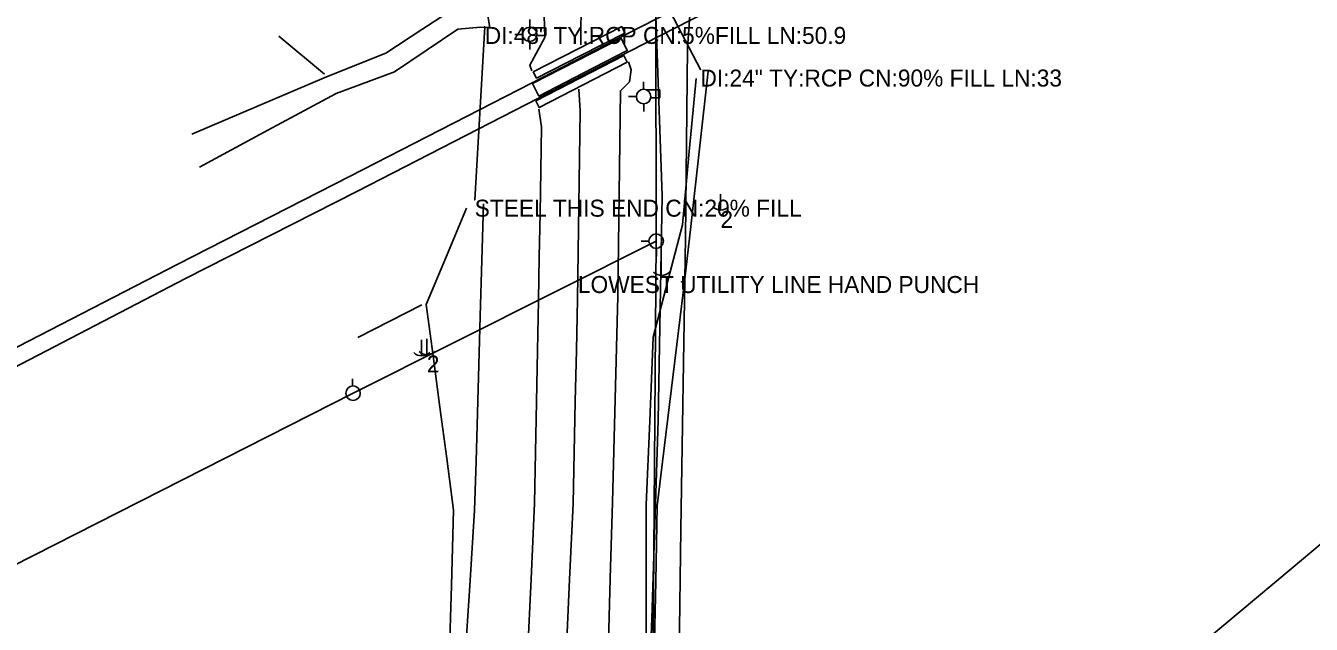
# Model space of a CAD drawing. Extents: x 1707085 to 1720058, y 548761 to 560063.
# Drawn here: x 1712315.3 to 1712693.8, y 549836.8 to 550013 of the extents above; entities that cross this region are included whole.
import ezdxf

# ---------------------------------------------------------------- set-up
doc = ezdxf.new("R2010")
doc.units = 0
for name, color, linetype in [('22', 7, 'Continuous'), ('3', 7, 'Continuous'), ('R_Water Annot', 7, 'Continuous'), ('S_DRG_PT_SYM', 7, 'Continuous'), ('S_EDGE_PAVEMENT', 7, 'Continuous'), ('S_ELECTRIC_UTILITIES_ANNOT', 7, 'Continuous'), ('S_GAS_UTILITIES', 7, 'Continuous'), ('S_MSC_PT_SYM', 7, 'Continuous'), ('S_PAVEMENT_CROWN', 7, 'Continuous'), ('S_SIDE_DRAIN_ANNOT', 7, 'Continuous'), ('S_UTILITY_POLE', 7, 'Continuous'), ('S_UTILITY_POLE_ANNOT', 7, 'Continuous'), ('S_UTL_PT_SYM', 7, 'Continuous')]:
    doc.layers.add(name, color=color, linetype=linetype)

msp = doc.modelspace()

# ---------------------------------------------------------------- linework, layer by layer
for points in [[(1712449.32, 550057.1), (1712439.4, 550041.45), (1712442.55, 550018.72), (1712431.95, 550011.83), (1712421.36, 550004.94), (1712403.89, 549997.96), (1712384.06, 549989.51), (1712364.23, 549981.06)], [(1712452.56, 550057.8), (1712451.58, 550039.11), (1712450.6, 550020.42), (1712452, 550012.47), (1712449.18, 550012.57), (1712442.51, 550011.92), (1712423.88, 549999.42), (1712406.74, 549993.06), (1712386.61, 549982.2), (1712366.49, 549971.34)], [(1712403.31, 549998.67), (1712389.85, 550009.89)], [(1712516.18, 549999.6), (1712513.67, 549976.72), (1712511.17, 549953.84), (1712509.32, 549938.49), (1712507.47, 549923.14), (1712505.92, 549910.27), (1712504.37, 549897.4), (1712502.81, 549884.54), (1712501.26, 549871.67), (1712500.82, 549849.4), (1712500.38, 549827.13), (1712500.22, 549810.79), (1712500.05, 549794.46), (1712518.8, 549793.53), (1712537.55, 549792.61), (1712556.3, 549791.68), (1712575.05, 549790.76), (1712588.15, 549794.26), (1712601.26, 549797.76), (1712614.36, 549801.26), (1712627.46, 549804.76)], [(1712512.67, 549997.47), (1712510.66, 549975.93), (1712508.64, 549954.38), (1712504.35, 549937.83), (1712500.05, 549921.28), (1712499.04, 549896.62), (1712498.02, 549871.95), (1712498, 549849.31), (1712497.97, 549826.67)], [(1712450.13, 549960.52), (1712449.65, 549943.98), (1712449.16, 549927.44), (1712448.74, 549913.18), (1712448.32, 549898.91), (1712447.91, 549884.64), (1712447.49, 549870.37), (1712446.03, 549848.12), (1712444.58, 549825.86), (1712443.13, 549803.61), (1712441.67, 549781.36), (1712441.33, 549777.17), (1712439.1, 549763.29), (1712436.87, 549749.41), (1712435.25, 549741.91), (1712433.87, 549729.68), (1712428.48, 549723.04), (1712424.13, 549714.66), (1712415.06, 549699.57), (1712406, 549684.47), (1712392.91, 549666.42), (1712379.82, 549648.36), (1712369.03, 549636.94), (1712358.25, 549625.52)], [(1712445.12, 549959.28), (1712439.18, 549945.1), (1712433.24, 549930.92), (1712435.25, 549915.78), (1712437.26, 549900.65), (1712439.28, 549885.52), (1712441.29, 549870.38), (1712440.63, 549848.2), (1712439.98, 549826.01), (1712439.32, 549803.82), (1712438.67, 549781.64), (1712438.35, 549777.49), (1712437.11, 549764.29), (1712435.86, 549751.09), (1712435.54, 549749.77), (1712432.09, 549741.95), (1712428.34, 549731.72), (1712421.02, 549715.67), (1712413.21, 549700.34), (1712405.41, 549685)], [(1712413.13, 549921.2), (1712431.91, 549930.83)], [(1712657.85, 549827.96), (1712672.84, 549840.5), (1712687.84, 549853.05), (1712700.01, 549863.27)]]:
    msp.add_lwpolyline(points)
at = {"layer": '22'}
for p, q in [((1712492.4, 550010.61), (1712547.07, 550038.73)), ((1712493.21, 550005.51), (1712555.91, 550037.61)), ((1712463.69, 550012.56), (1712463.69, 550014.8)), ((1712461.6, 550010.42), (1712459.27, 550010.42)), ((1712464.27, 549996.1), (1712492.4, 550010.61)), ((1712468.49, 550012.4), (1712464.62, 550012.4)), ((1712468.49, 550010.08), (1712468.49, 550012.4)), ((1712463.77, 550006.01), (1712463.77, 550008.33)), ((1712468.49, 550010.08), (1712465.78, 550010.08)), ((1712466.25, 549991.68), (1712493.21, 550005.51)), ((1712410.66, 549968.61), (1712464.27, 549996.1)), ((1712497.22, 549994.24), (1712497.22, 549996.48)), ((1712412.81, 549964.19), (1712466.25, 549991.68)), ((1712495.13, 549992.1), (1712492.8, 549992.1)), ((1712502.02, 549994.08), (1712498.15, 549994.08)), ((1712502.02, 549991.76), (1712499.31, 549991.76)), ((1712502.02, 549991.76), (1712502.02, 549994.08)), ((1712497.3, 549987.69), (1712497.3, 549990.01)), ((1712360.1, 549942.79), (1712410.66, 549968.61)), ((1712362.36, 549938.57), (1712412.81, 549964.19)), ((1712304.76, 549914.22), (1712360.1, 549942.79)), ((1712306.81, 549909.7), (1712362.36, 549938.57))]:
    msp.add_line(p, q, dxfattribs=at)
for points in [[(1712464.7, 549999.43), (1712465.72, 549997.54), (1712478.71, 550004.17), (1712491.7, 550010.8), (1712490.77, 550012.73), (1712477.74, 550006.08)], [(1712490.63, 550009.36), (1712492.42, 550005.68), (1712479.43, 549998.97), (1712466.43, 549992.25), (1712464.54, 549995.95), (1712477.59, 550002.65)], [(1712465.46, 549990.9), (1712466.51, 549988.88), (1712479.47, 549995.59), (1712492.43, 550002.29), (1712491.41, 550004.18), (1712478.44, 549997.54)]]:
    msp.add_lwpolyline(points, close=True, dxfattribs=at)
for centre in [(1712463.69, 550010.44), (1712497.22, 549992.12)]:
    msp.add_circle(centre, 2.13, dxfattribs=at)
at = {"layer": '3'}
for p, q in [((1712513.96, 550000.07), (1712498.6, 550029.64)), ((1712450.45, 550012.61), (1712447.5, 549961.76))]:
    msp.add_line(p, q, dxfattribs=at)
at = {"layer": 'R_Water Annot'}
for p, q in [((1712511.52, 550025.76), (1712510.15, 550006.45)), ((1712510.15, 550006.45), (1712509.57, 549950.51)), ((1712509.57, 549950.51), (1712508.17, 549864.7)), ((1712508.17, 549864.7), (1712507.43, 549804.25))]:
    msp.add_line(p, q, dxfattribs=at)
at = {"layer": 'S_DRG_PT_SYM'}
for points in [[(1712450.45, 550012.61), (1712450.45, 550012.66), (1712450.45, 550012.61), (1712450.4, 550012.61), (1712450.45, 550012.61), (1712450.45, 550012.56), (1712450.45, 550012.61), (1712450.5, 550012.61)], [(1712513.96, 550000.07), (1712513.96, 550000.12), (1712513.96, 550000.07), (1712513.91, 550000.07), (1712513.96, 550000.07), (1712513.96, 550000.02), (1712513.96, 550000.07), (1712514.01, 550000.07)], [(1712447.5, 549961.76), (1712447.5, 549961.81), (1712447.5, 549961.76), (1712447.45, 549961.76), (1712447.5, 549961.76), (1712447.5, 549961.71), (1712447.5, 549961.76), (1712447.55, 549961.76)]]:
    msp.add_lwpolyline(points, dxfattribs=at)
at = {"layer": 'S_EDGE_PAVEMENT'}
for points in [[(1712467.77, 550022.58), (1712468.12, 550009.49), (1712463.76, 550001.4), (1712464.35, 549999.67)], [(1712492.77, 550002.31), (1712493.53, 550000.02), (1712493.07, 549996.49), (1712490.38, 549993.82), (1712490.2, 549978.71), (1712490.03, 549963.6), (1712489.85, 549948.48), (1712489.68, 549933.37), (1712489.27, 549918.2), (1712488.86, 549903.03), (1712488.45, 549887.86), (1712488.04, 549872.68), (1712487.4, 549850.22), (1712486.77, 549827.75)], [(1712492.77, 550002.31), (1712493.53, 550000.02), (1712493.07, 549996.49), (1712490.38, 549993.82), (1712490.2, 549978.71), (1712490.03, 549963.6), (1712489.85, 549948.48), (1712489.68, 549933.37), (1712489.27, 549918.2), (1712488.86, 549903.03), (1712488.45, 549887.86), (1712488.04, 549872.68), (1712487.4, 549850.22), (1712486.77, 549827.75)], [(1712466.43, 549988.37), (1712467.17, 549983.23), (1712466.95, 549970.47), (1712466.73, 549957.72), (1712466.52, 549944.96), (1712466.3, 549932.21), (1712466, 549917.25), (1712465.71, 549902.29), (1712465.42, 549887.33), (1712465.12, 549872.38), (1712464.08, 549850.01), (1712463.03, 549827.64)], [(1712466.43, 549988.37), (1712467.17, 549983.23), (1712466.95, 549970.47), (1712466.73, 549957.72), (1712466.52, 549944.96), (1712466.3, 549932.21), (1712466, 549917.25), (1712465.71, 549902.29), (1712465.42, 549887.33), (1712465.12, 549872.38), (1712464.08, 549850.01), (1712463.03, 549827.64)]]:
    msp.add_lwpolyline(points, dxfattribs=at)
at = {"layer": 'S_GAS_UTILITIES'}
for p, q in [((1712500.56, 550022.14), (1712502.65, 549962.94)), ((1712502.65, 549962.94), (1712501.5, 549896.8)), ((1712501.5, 549896.8), (1712499.66, 549838.6)), ((1712499.66, 549838.6), (1712496.86, 549773.59))]:
    msp.add_line(p, q, dxfattribs=at)
at = {"layer": 'S_MSC_PT_SYM'}
for points in [[(1712492.4, 550010.61), (1712492.4, 550010.66), (1712492.4, 550010.61), (1712492.35, 550010.61), (1712492.4, 550010.61), (1712492.4, 550010.56), (1712492.4, 550010.61), (1712492.45, 550010.61)], [(1712493.21, 550005.51), (1712493.21, 550005.56), (1712493.21, 550005.51), (1712493.16, 550005.51), (1712493.21, 550005.51), (1712493.21, 550005.46), (1712493.21, 550005.51), (1712493.26, 550005.51)], [(1712464.27, 549996.1), (1712464.27, 549996.15), (1712464.27, 549996.1), (1712464.22, 549996.1), (1712464.27, 549996.1), (1712464.27, 549996.05), (1712464.27, 549996.1), (1712464.32, 549996.1)], [(1712466.25, 549991.68), (1712466.25, 549991.73), (1712466.25, 549991.68), (1712466.2, 549991.68), (1712466.25, 549991.68), (1712466.25, 549991.63), (1712466.25, 549991.68), (1712466.3, 549991.68)], [(1712410.66, 549968.61), (1712410.66, 549968.66), (1712410.66, 549968.61), (1712410.61, 549968.61), (1712410.66, 549968.61), (1712410.66, 549968.56), (1712410.66, 549968.61), (1712410.71, 549968.61)], [(1712412.81, 549964.19), (1712412.81, 549964.24), (1712412.81, 549964.19), (1712412.76, 549964.19), (1712412.81, 549964.19), (1712412.81, 549964.14), (1712412.81, 549964.19), (1712412.86, 549964.19)], [(1712360.1, 549942.79), (1712360.1, 549942.84), (1712360.1, 549942.79), (1712360.05, 549942.79), (1712360.1, 549942.79), (1712360.1, 549942.74), (1712360.1, 549942.79), (1712360.15, 549942.79)], [(1712362.36, 549938.57), (1712362.36, 549938.62), (1712362.36, 549938.57), (1712362.31, 549938.57), (1712362.36, 549938.57), (1712362.36, 549938.52), (1712362.36, 549938.57), (1712362.41, 549938.57)]]:
    msp.add_lwpolyline(points, dxfattribs=at)
at = {"layer": 'S_PAVEMENT_CROWN'}
for points in [[(1712478.75, 550007.31), (1712478.84, 550022.01)], [(1712478.84, 550022.01), (1712478.75, 550007.31)], [(1712478.11, 549994.32), (1712478.54, 549987.96), (1712478.34, 549974.08), (1712478.15, 549960.21), (1712477.95, 549946.33), (1712477.76, 549932.46), (1712477.43, 549917.42), (1712477.1, 549902.39), (1712476.78, 549887.35), (1712476.45, 549872.32), (1712475.42, 549849.98), (1712474.4, 549827.65)], [(1712478.11, 549994.32), (1712478.54, 549987.96), (1712478.34, 549974.08), (1712478.15, 549960.21), (1712477.95, 549946.33), (1712477.76, 549932.46), (1712477.43, 549917.42), (1712477.1, 549902.39), (1712476.78, 549887.35), (1712476.45, 549872.32), (1712475.42, 549849.98), (1712474.4, 549827.65)]]:
    msp.add_lwpolyline(points, dxfattribs=at)
at = {"layer": 'S_UTILITY_POLE'}
for p, q in [((1712519.82, 549963.4), (1712519.82, 549958.67)), ((1712500.91, 549951.68), (1712500.91, 549953.92)), ((1712498.81, 549949.54), (1712496.49, 549949.54)), ((1712500.98, 549945.13), (1712500.98, 549947.45)), ((1712502.44, 549944.19), (1712502.44, 549939.47)), ((1712431.85, 549920.5), (1712431.85, 549915.77)), ((1712433.4, 549920.84), (1712433.4, 549916.11)), ((1712411.58, 549906.93), (1712411.58, 549909.04))]:
    msp.add_line(p, q, dxfattribs=at)
for points in [[(1712497.7, 549518.48), (1712500.91, 549949.56), (1712500.58, 550149.34), (1712502.49, 550416.34), (1712509.79, 550634.49), (1712512.76, 550903.53), (1712513.37, 551033.49), (1712513.87, 551133.13), (1712444.45, 551132.54)], [(1711064.39, 549251.72), (1711313.01, 549347.35), (1711526.73, 549455.46), (1711746.33, 549566.96), (1712411.7, 549904.79), (1712500.91, 549949.56)]]:
    msp.add_lwpolyline(points, dxfattribs=at)
for centre in [(1712500.91, 549949.56), (1712411.7, 549904.79)]:
    msp.add_circle(centre, 2.13, dxfattribs=at)
for centre in [(1712519.88, 549962.1), (1712502.5, 549942.89), (1712431.91, 549919.2), (1712433.46, 549919.53)]:
    msp.add_arc(centre, 3.41, 226.3972, 313.6028, dxfattribs=at)
at = {"layer": 'S_UTL_PT_SYM'}
for points in [[(1712510.15, 550006.45), (1712510.15, 550006.5), (1712510.15, 550006.45), (1712510.1, 550006.45), (1712510.15, 550006.45), (1712510.15, 550006.4), (1712510.15, 550006.45), (1712510.2, 550006.45)], [(1712502.65, 549962.94), (1712502.65, 549962.99), (1712502.65, 549962.94), (1712502.6, 549962.94), (1712502.65, 549962.94), (1712502.65, 549962.89), (1712502.65, 549962.94), (1712502.7, 549962.94)], [(1712509.57, 549950.51), (1712509.57, 549950.56), (1712509.57, 549950.51), (1712509.52, 549950.51), (1712509.57, 549950.51), (1712509.57, 549950.46), (1712509.57, 549950.51), (1712509.62, 549950.51)], [(1712477.88, 549939.29), (1712477.88, 549939.34), (1712477.88, 549939.29), (1712477.83, 549939.29), (1712477.88, 549939.29), (1712477.88, 549939.24), (1712477.88, 549939.29), (1712477.93, 549939.29)], [(1712508.37, 549937.62), (1712508.37, 549937.67), (1712508.37, 549937.62), (1712508.32, 549937.62), (1712508.37, 549937.62), (1712508.37, 549937.57), (1712508.37, 549937.62), (1712508.42, 549937.62)], [(1712501.5, 549896.8), (1712501.5, 549896.85), (1712501.5, 549896.8), (1712501.45, 549896.8), (1712501.5, 549896.8), (1712501.5, 549896.75), (1712501.5, 549896.8), (1712501.55, 549896.8)], [(1712508.17, 549864.7), (1712508.17, 549864.75), (1712508.17, 549864.7), (1712508.12, 549864.7), (1712508.17, 549864.7), (1712508.17, 549864.65), (1712508.17, 549864.7), (1712508.22, 549864.7)], [(1712499.66, 549838.6), (1712499.66, 549838.65), (1712499.66, 549838.6), (1712499.61, 549838.6), (1712499.66, 549838.6), (1712499.66, 549838.55), (1712499.66, 549838.6), (1712499.71, 549838.6)]]:
    msp.add_lwpolyline(points, dxfattribs=at)

# ---------------------------------------------------------------- texts
at = {"layer": 'S_ELECTRIC_UTILITIES_ANNOT'}
msp.add_text('LOWEST UTILITY LINE HAND PUNCH', height=5, dxfattribs=at).set_placement((1712477.88, 549934.29))
at = {"layer": 'S_SIDE_DRAIN_ANNOT'}
for s, p in [('DI:48" TY:RCP CN:5%FILL LN:50.9', (1712450.45, 550007.61)), ('DI:24" TY:RCP CN:90% FILL LN:33', (1712513.96, 549995.07)), ('STEEL THIS END CN:20% FILL', (1712447.5, 549956.76))]:
    msp.add_text(s, height=5, dxfattribs=at).set_placement(p)
at = {"layer": 'S_UTILITY_POLE_ANNOT'}
for p in [(1712519.83, 549953.46), (1712433.41, 549910.89)]:
    msp.add_text('2', height=5, dxfattribs=at).set_placement(p)

doc.saveas('drawing.dxf')
